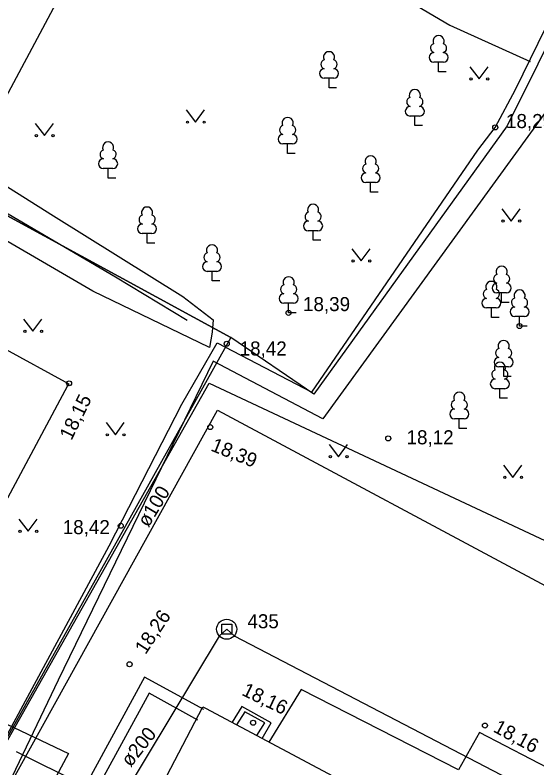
# Model space of a CAD drawing. Extents: x 713540 to 713867, y 6589774 to 6590061.
# Drawn here: x 713776.03 to 713801.99, y 6589910.9 to 6589948.37 of the extents above; entities that cross this region are included whole.
import ezdxf

# ---------------------------------------------------------------- set-up
doc = ezdxf.new("R2010")
doc.units = 0
for name, color, linetype in [('AED', 7, 'Continuous'), ('DKAEV', 7, 'Continuous'), ('HALJASTUS', 7, 'Continuous'), ('HOONE', 7, 'Continuous'), ('HOONEDET', 7, 'Continuous'), ('KORGUS', 7, 'Continuous'), ('PUU', 7, 'Continuous'), ('SIKAEV', 7, 'Continuous'), ('SITRASS', 7, 'Continuous'), ('TEE', 7, 'Continuous'), ('TORU NR', 7, 'Continuous'), ('TTRASS', 7, 'Continuous'), ('Слой 1', 7, 'Continuous')]:
    doc.layers.add(name, color=color, linetype=linetype)

msp = doc.modelspace()

# ---------------------------------------------------------------- linework, layer by layer
at = {"layer": 'AED'}
msp.add_lwpolyline([(713767.762, 6589909.249), (713772.443, 6589906.664), (713772.921, 6589907.533), (713780.72, 6589921.96), (713784.33, 6589929.01), (713786.08, 6589932.05), (713790.79, 6589929.6), (713799.05, 6589941.64), (713799.92, 6589942.78), (713800.93, 6589944.67), (713803.18, 6589949.29), (713806.07, 6589954.43), (713810.4, 6589962.76), (713799.4, 6589967.72), (713795.11, 6589969.78), (713786.56, 6589953.97)], dxfattribs=at)
at = {"layer": 'DKAEV'}
for p, q in [((713786.31, 6589917.55), (713786.31, 6589918.05)), ((713786.31, 6589918.05), (713786.81, 6589918.05)), ((713786.81, 6589918.05), (713786.81, 6589917.55)), ((713786.81, 6589917.55), (713786.31, 6589917.55))]:
    msp.add_line(p, q, dxfattribs=at)
msp.add_circle((713786.56, 6589917.8), 0.5, dxfattribs=at)
at = {"layer": 'HALJASTUS'}
for p, q in [((713798.657, 6589945.797), (713799.12, 6589945.19)), ((713799.12, 6589945.19), (713799.566, 6589945.797)), ((713784.547, 6589943.647), (713785.01, 6589943.04)), ((713785.01, 6589943.04), (713785.456, 6589943.647)), ((713777.027, 6589942.977), (713777.49, 6589942.37)), ((713777.49, 6589942.37), (713777.936, 6589942.977)), ((713800.247, 6589938.727), (713800.71, 6589938.12)), ((713800.71, 6589938.12), (713801.156, 6589938.727)), ((713792.787, 6589936.737), (713793.25, 6589936.13)), ((713793.25, 6589936.13), (713793.696, 6589936.737)), ((713776.457, 6589933.237), (713776.92, 6589932.63)), ((713776.92, 6589932.63), (713777.366, 6589933.237)), ((713780.557, 6589928.087), (713781.02, 6589927.48)), ((713781.02, 6589927.48), (713781.466, 6589928.087)), ((713791.657, 6589926.997), (713792.12, 6589926.39)), ((713792.12, 6589926.39), (713792.566, 6589926.997)), ((713800.337, 6589925.967), (713800.8, 6589925.36)), ((713800.8, 6589925.36), (713801.246, 6589925.967)), ((713776.217, 6589923.287), (713776.68, 6589922.68)), ((713776.68, 6589922.68), (713777.126, 6589923.287))]:
    msp.add_line(p, q, dxfattribs=at)
for points in [[(713800.49, 6589967.31), (713798.67, 6589963.56), (713795.35, 6589956.78), (713792.37, 6589950.97), (713793.24, 6589950.48), (713797.66, 6589947.86), (713801.66, 6589946.06)], [(713760.304, 6589956.722), (713758.16, 6589952.94), (713757.47, 6589951.68), (713757.33, 6589950.37), (713757.8, 6589949.47), (713758.84, 6589948.39), (713761.14, 6589947.03), (713764.66, 6589945.48), (713769.93, 6589943.18), (713772.72, 6589941.66), (713777.94, 6589938.37), (713784.38, 6589934.37), (713785.89, 6589933.2), (713785.84, 6589932.59), (713785.7, 6589931.83)], [(713784.59, 6589933.17), (713781.02, 6589935.33), (713772.33, 6589940.41), (713769.84, 6589941.82), (713765.68, 6589943.71), (713762.99, 6589944.84), (713760.91, 6589946.1), (713756.58, 6589948.8), (713756.13, 6589949.298)], [(713785.7, 6589931.83), (713779.9, 6589934.62), (713773.36, 6589938.43), (713770.69, 6589940.16), (713767.63, 6589941.77), (713761.39, 6589944.57), (713757.43, 6589946.56), (713755.59, 6589947.74), (713755.446, 6589947.863)]]:
    msp.add_lwpolyline(points, dxfattribs=at)
for centre in [(713798.719, 6589945.19), (713799.548, 6589945.19), (713784.609, 6589943.04), (713785.438, 6589943.04), (713777.089, 6589942.37), (713777.918, 6589942.37), (713800.309, 6589938.12), (713801.138, 6589938.12), (713792.849, 6589936.13), (713793.678, 6589936.13), (713776.519, 6589932.63), (713777.348, 6589932.63), (713780.619, 6589927.48), (713781.448, 6589927.48), (713791.719, 6589926.39), (713792.548, 6589926.39), (713800.399, 6589925.36), (713801.228, 6589925.36), (713776.279, 6589922.68), (713777.108, 6589922.68)]:
    msp.add_circle(centre, 0.055, dxfattribs=at)
at = {"layer": 'HOONE'}
for points in [[(713853.13, 6590055.49), (713847.71, 6590042.61), (713840.88, 6590026.99), (713847.68, 6590019.43), (713836.38, 6589998.1), (713820.11, 6589968.4), (713812.16, 6589957.32), (713804.57, 6589946.51), (713791.35, 6589928.27), (713785.88, 6589931.15), (713778.18, 6589915.27), (713769.3, 6589896.72), (713774.33, 6589893.89), (713767.85, 6589880.54), (713761.86, 6589868.49), (713755.914, 6589856.728), (713753.12, 6589851.2), (713744.71, 6589834.75), (713742.63, 6589834)], [(713772.03, 6589933.66), (713778.7, 6589930.01), (713778.64, 6589929.91), (713772.65, 6589918.74), (713766.16, 6589922.39), (713772.03, 6589933.66)], [(713760.52, 6589918.72), (713760.97, 6589918.8), (713761.59, 6589919.93), (713768.07, 6589916.66), (713778.69, 6589911.61), (713767.43, 6589890.63), (713753, 6589864.84), (713751.627, 6589862.341)], [(713786.56, 6589917.8), (713786.19, 6589917.45), (713776.472, 6589901.302)], [(713786.56, 6589917.8), (713786.93, 6589917.47), (713812.67, 6589904.07)], [(713806.56, 6589906.42), (713803.33, 6589908.13), (713804.24, 6589910.01), (713799.14, 6589912.67), (713798.09, 6589910.8), (713790.27, 6589914.8), (713788.66, 6589912.19)], [(713779.206, 6589902.11), (713785.37, 6589913.94), (713785.5, 6589913.88), (713807.8, 6589901.99), (713801.894, 6589890.118), (713779.206, 6589902.11)]]:
    msp.add_lwpolyline(points, dxfattribs=at)
at = {"layer": 'HOONEDET'}
for points in [[(713785.417, 6589913.801), (713782.47, 6589915.425), (713773.549, 6589899.035), (713774.045, 6589898.794), (713773.561, 6589899.028), (713773.532, 6589898.973), (713799.241, 6589885.198), (713801.894, 6589890.118)], [(713785.13, 6589913.279), (713782.707, 6589914.614), (713774.044, 6589898.795)], [(713788.33, 6589912.37), (713788.78, 6589913.14), (713787.31, 6589913.95), (713786.83, 6589913.17)], [(713788.06, 6589912.52), (713788.46, 6589913.15), (713787.47, 6589913.69), (713787.05, 6589913.05)]]:
    msp.add_lwpolyline(points, dxfattribs=at)
at = {"layer": 'KORGUS'}
for centre in [(713799.92, 6589942.78), (713789.64, 6589933.55), (713801.13, 6589932.89), (713786.56, 6589932.01), (713778.72, 6589930.04), (713785.74, 6589927.86), (713794.6, 6589927.3), (713781.29, 6589922.95), (713781.73, 6589916.06), (713787.87, 6589913.15), (713799.41, 6589913.01)]:
    msp.add_circle(centre, 0.125, dxfattribs=at)
at = {"layer": 'PUU'}
for p, q in [((713797.34, 6589946.025), (713796.86, 6589946.025)), ((713797.1, 6589945.55), (713797.1, 6589946.025)), ((713797.48, 6589945.55), (713797.1, 6589945.55)), ((713791.89, 6589945.225), (713791.41, 6589945.225)), ((713791.65, 6589944.75), (713791.65, 6589945.225)), ((713792.03, 6589944.75), (713791.65, 6589944.75)), ((713796.16, 6589943.345), (713795.68, 6589943.345)), ((713795.92, 6589942.87), (713795.92, 6589943.345)), ((713796.3, 6589942.87), (713795.92, 6589942.87)), ((713789.83, 6589941.955), (713789.35, 6589941.955)), ((713789.59, 6589941.48), (713789.59, 6589941.955)), ((713789.97, 6589941.48), (713789.59, 6589941.48)), ((713780.9, 6589940.735), (713780.42, 6589940.735)), ((713780.66, 6589940.26), (713780.66, 6589940.735)), ((713781.04, 6589940.26), (713780.66, 6589940.26)), ((713793.96, 6589940.035), (713793.48, 6589940.035)), ((713793.72, 6589939.56), (713793.72, 6589940.035)), ((713794.1, 6589939.56), (713793.72, 6589939.56)), ((713791.1, 6589937.635), (713790.62, 6589937.635)), ((713790.86, 6589937.16), (713790.86, 6589937.635)), ((713782.84, 6589937.495), (713782.36, 6589937.495)), ((713782.6, 6589937.02), (713782.6, 6589937.495)), ((713782.98, 6589937.02), (713782.6, 6589937.02)), ((713791.24, 6589937.16), (713790.86, 6589937.16)), ((713786.07, 6589935.615), (713785.59, 6589935.615)), ((713785.83, 6589935.14), (713785.83, 6589935.615)), ((713786.21, 6589935.14), (713785.83, 6589935.14)), ((713800.48, 6589934.545), (713800, 6589934.545)), ((713800.24, 6589934.07), (713800.24, 6589934.545)), ((713789.88, 6589934.025), (713789.4, 6589934.025)), ((713789.64, 6589933.55), (713789.64, 6589934.025)), ((713800.62, 6589934.07), (713800.24, 6589934.07)), ((713790.02, 6589933.55), (713789.64, 6589933.55)), ((713799.97, 6589933.795), (713799.49, 6589933.795)), ((713799.73, 6589933.32), (713799.73, 6589933.795)), ((713800.11, 6589933.32), (713799.73, 6589933.32)), ((713801.37, 6589933.365), (713800.89, 6589933.365)), ((713801.13, 6589932.89), (713801.13, 6589933.365)), ((713801.51, 6589932.89), (713801.13, 6589932.89)), ((713800.58, 6589930.855), (713800.1, 6589930.855)), ((713800.34, 6589930.38), (713800.34, 6589930.855)), ((713800.72, 6589930.38), (713800.34, 6589930.38)), ((713800.39, 6589929.775), (713799.91, 6589929.775)), ((713800.15, 6589929.3), (713800.15, 6589929.775)), ((713800.53, 6589929.3), (713800.15, 6589929.3)), ((713798.37, 6589928.275), (713797.89, 6589928.275)), ((713798.13, 6589927.8), (713798.13, 6589928.275)), ((713798.51, 6589927.8), (713798.13, 6589927.8))]:
    msp.add_line(p, q, dxfattribs=at)
for centre, radius, start, end in [((713797.1, 6589947.07), 0.277, 332.5799, 207.4201), ((713796.93, 6589946.723), 0.233, 109.0217, 253.1415), ((713797.27, 6589946.723), 0.233, 286.8508, 70.9859), ((713791.65, 6589946.27), 0.277, 332.5799, 207.4201), ((713796.863, 6589946.262), 0.238, 90.0016, 269.3953), ((713797.337, 6589946.262), 0.238, 270.6047, 89.9984), ((713791.48, 6589945.923), 0.233, 109.0217, 253.1415), ((713791.82, 6589945.923), 0.233, 286.8508, 70.9859), ((713791.413, 6589945.462), 0.238, 90.0016, 269.3953), ((713791.887, 6589945.462), 0.238, 270.6047, 89.9984), ((713795.92, 6589944.39), 0.277, 332.5799, 207.4201), ((713795.75, 6589944.043), 0.233, 109.0217, 253.1415), ((713796.09, 6589944.043), 0.233, 286.8508, 70.9859), ((713795.683, 6589943.582), 0.238, 90.0016, 269.3953), ((713796.157, 6589943.582), 0.238, 270.6047, 89.9984), ((713789.59, 6589943), 0.277, 332.5799, 207.4201), ((713789.42, 6589942.653), 0.233, 109.0217, 253.1415), ((713789.76, 6589942.653), 0.233, 286.8508, 70.9859), ((713789.353, 6589942.192), 0.238, 90.0016, 269.3953), ((713789.827, 6589942.192), 0.238, 270.6047, 89.9984), ((713780.66, 6589941.78), 0.277, 332.5799, 207.4201), ((713780.49, 6589941.433), 0.233, 109.0217, 253.1415), ((713780.83, 6589941.433), 0.233, 286.8508, 70.9859), ((713793.72, 6589941.08), 0.277, 332.5799, 207.4201), ((713780.423, 6589940.972), 0.238, 90.0016, 269.3953), ((713780.897, 6589940.972), 0.238, 270.6047, 89.9984), ((713793.55, 6589940.733), 0.233, 109.0217, 253.1415), ((713793.89, 6589940.733), 0.233, 286.8508, 70.9859), ((713793.483, 6589940.272), 0.238, 90.0016, 269.3953), ((713793.957, 6589940.272), 0.238, 270.6047, 89.9984), ((713782.6, 6589938.54), 0.277, 332.5799, 207.4201), ((713790.86, 6589938.68), 0.277, 332.5799, 207.4201), ((713782.43, 6589938.193), 0.233, 109.0217, 253.1415), ((713782.77, 6589938.193), 0.233, 286.8508, 70.9859), ((713790.69, 6589938.333), 0.233, 109.0217, 253.1415), ((713791.03, 6589938.333), 0.233, 286.8508, 70.9859), ((713782.363, 6589937.732), 0.238, 90.0016, 269.3953), ((713782.837, 6589937.732), 0.238, 270.6047, 89.9984), ((713790.623, 6589937.872), 0.238, 90.0016, 269.3953), ((713791.097, 6589937.872), 0.238, 270.6047, 89.9984), ((713785.83, 6589936.66), 0.277, 332.5799, 207.4201), ((713785.66, 6589936.313), 0.233, 109.0217, 253.1415), ((713786, 6589936.313), 0.233, 286.8508, 70.9859), ((713785.593, 6589935.852), 0.238, 90.0016, 269.3953), ((713786.067, 6589935.852), 0.238, 270.6047, 89.9984), ((713800.24, 6589935.59), 0.277, 332.5799, 207.4201), ((713789.64, 6589935.07), 0.277, 332.5799, 207.4201), ((713800.07, 6589935.243), 0.233, 109.0217, 253.1415), ((713800.41, 6589935.243), 0.233, 286.8508, 70.9859), ((713789.47, 6589934.723), 0.233, 109.0217, 253.1415), ((713789.81, 6589934.723), 0.233, 286.8508, 70.9859), ((713799.73, 6589934.84), 0.277, 332.5799, 207.4201), ((713800.003, 6589934.782), 0.238, 90.0016, 269.3953), ((713800.477, 6589934.782), 0.238, 270.6047, 89.9984), ((713799.56, 6589934.493), 0.233, 109.0217, 253.1415), ((713799.9, 6589934.493), 0.233, 286.8508, 70.9859), ((713801.13, 6589934.41), 0.277, 332.5799, 207.4201), ((713789.403, 6589934.262), 0.238, 90.0016, 269.3953), ((713789.877, 6589934.262), 0.238, 270.6047, 89.9984), ((713799.493, 6589934.032), 0.238, 90.0016, 269.3953), ((713799.967, 6589934.032), 0.238, 270.6047, 89.9984), ((713800.96, 6589934.063), 0.233, 109.0217, 253.1415), ((713801.3, 6589934.063), 0.233, 286.8508, 70.9859), ((713800.893, 6589933.602), 0.238, 90.0016, 269.3953), ((713801.367, 6589933.602), 0.238, 270.6047, 89.9984), ((713800.34, 6589931.9), 0.277, 332.5799, 207.4201), ((713800.17, 6589931.553), 0.233, 109.0217, 253.1415), ((713800.51, 6589931.553), 0.233, 286.8508, 70.9859), ((713800.103, 6589931.092), 0.238, 90.0016, 269.3953), ((713800.577, 6589931.092), 0.238, 270.6047, 89.9984), ((713800.15, 6589930.82), 0.277, 332.5799, 207.4201), ((713799.98, 6589930.473), 0.233, 109.0217, 253.1415), ((713800.32, 6589930.473), 0.233, 286.8508, 70.9859), ((713799.913, 6589930.012), 0.238, 90.0016, 269.3953), ((713800.387, 6589930.012), 0.238, 270.6047, 89.9984), ((713798.13, 6589929.32), 0.277, 332.5799, 207.4201), ((713797.96, 6589928.973), 0.233, 109.0217, 253.1415), ((713798.3, 6589928.973), 0.233, 286.8508, 70.9859), ((713797.893, 6589928.512), 0.238, 90.0016, 269.3953), ((713798.367, 6589928.512), 0.238, 270.6047, 89.9984)]:
    msp.add_arc(centre, radius, start, end, dxfattribs=at)
at = {"layer": 'SITRASS'}
msp.add_lwpolyline([(713776.08, 6589911.71), (713782.55, 6589908.5)], dxfattribs=at)
at = {"layer": 'TEE'}
msp.add_lwpolyline([(713773.878, 6589906.656), (713786.11, 6589928.711), (713803.133, 6589919.587)], dxfattribs=at)
at = {"layer": 'TTRASS'}
msp.add_lwpolyline([(713761.73, 6589918.33), (713786.89, 6589965.52)], dxfattribs=at)
at = {"layer": 'Слой 1'}
for points in [[(713800.41, 6589978.59), (713796.9, 6589972.02), (713811.25, 6589964.46), (713800.51, 6589942.86), (713790.89, 6589929.51), (713786.76, 6589932.33), (713753.32, 6589950.56), (713774.49, 6589992.04)], [(713753.32, 6589950.56), (713786.76, 6589932.33), (713765.63, 6589894.55), (713732.87, 6589910.81)], [(713801.77, 6589877.49), (713765.63, 6589894.55), (713785.68, 6589930.05), (713821.49, 6589913.26)]]:
    msp.add_lwpolyline(points, close=True, dxfattribs=at)

# ---------------------------------------------------------------- texts
at = {"layer": 'KORGUS'}
for s, p in [('18,29', (713800.456, 6589942.745)), ('18,39', (713790.356, 6589933.635)), ('18,42', (713787.203, 6589931.425)), ('18,12', (713795.508, 6589927.005)), ('18,42', (713778.403, 6589922.535))]:
    msp.add_text(s, height=0.7, dxfattribs=at).set_placement(p)
for s, rotation, p in [('18,15', 63.9652, (713778.834, 6589927.164)), ('18,39', 338.0389, (713785.722, 6589926.705)), ('18,26', 56.7079, (713782.524, 6589916.51)), ('18,16', 334.3511, (713787.262, 6589914.544)), ('18,16', 331.6099, (713799.775, 6589912.727))]:
    msp.add_text(s, height=0.7, rotation=rotation, dxfattribs=at).set_placement(p)
at = {"layer": 'SIKAEV'}
msp.add_text('435', height=0.7, dxfattribs=at).set_placement((713787.59, 6589917.85))
at = {"layer": 'TORU NR'}
for s, rotation, p in [('ø100', 58.7707, (713782.662, 6589922.834)), ('ø200', 51.679, (713781.78, 6589910.904))]:
    msp.add_text(s, height=0.7, rotation=rotation, dxfattribs=at).set_placement(p)

doc.saveas('drawing.dxf')
